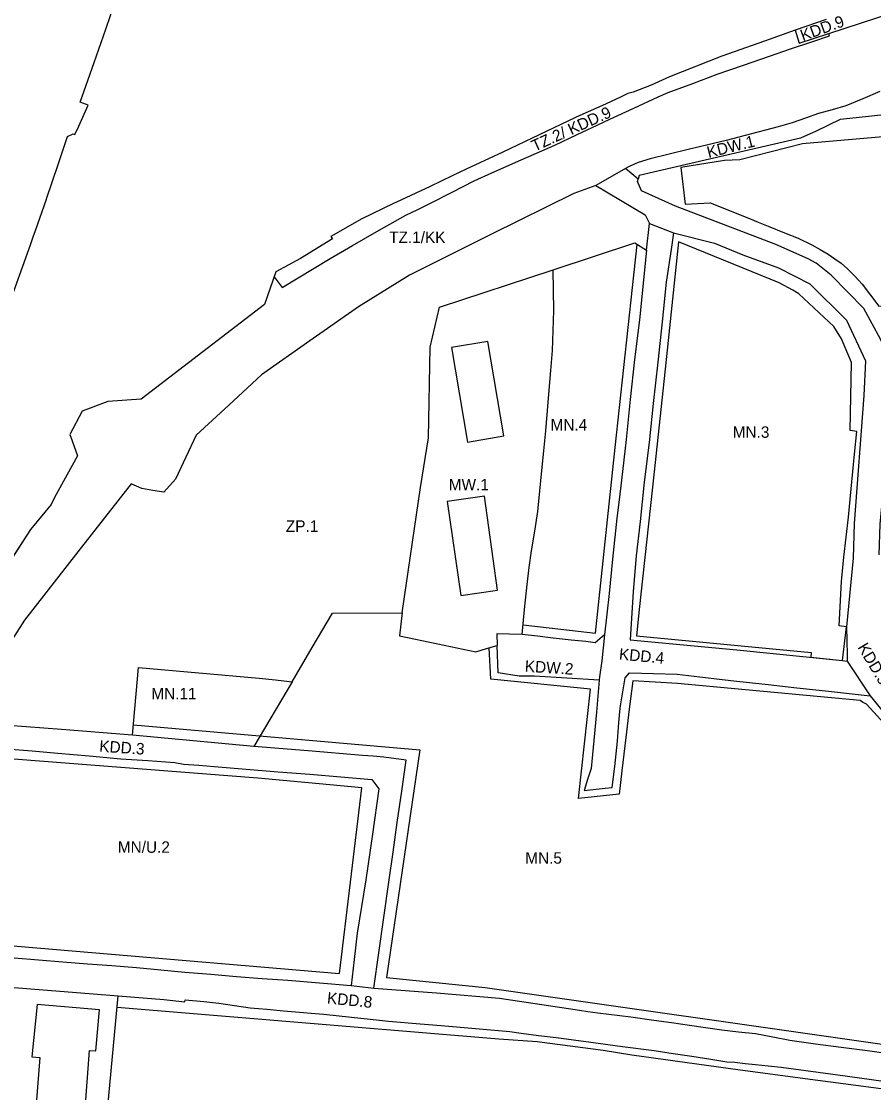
# Model space of a CAD drawing. Extents: x 7423274 to 7424514, y 5542390 to 5544261.
# Drawn here: x 7423710.5 to 7424007.3, y 5543609.4 to 5543982.5 of the extents above; entities that cross this region are included whole.
import ezdxf

# ---------------------------------------------------------------- set-up
doc = ezdxf.new("R2010")
doc.units = 0
for name, color, linetype in [('granica obszaru objętego planem', 7, 'Continuous'), ('LIN_Granica Planu', 7, 'Continuous'), ('linie rozgraniczające tereny o różnym przeznaczeniu lub różnych zasadach zagospodarowania', 7, 'Continuous'), ('nieprzekraczalna linia zabudowy', 7, 'Continuous'), ('oznaczenia terenów', 7, 'Continuous'), ('tereny dka ktorych obowiazuje_397', 7, 'Continuous')]:
    doc.layers.add(name, color=color, linetype=linetype)

msp = doc.modelspace()

# ---------------------------------------------------------------- linework, layer by layer
at = {"layer": 'granica obszaru objętego planem'}
msp.add_line((7423730.46, 5543946.09), (7423733.75, 5543953.36), dxfattribs=at)
for points in [[(7423733.75, 5543953.36), (7423730.98, 5543954.36), (7423735.85, 5543968.19), (7423739.86, 5543979.87), (7423744.43, 5543993.18), (7423748.18, 5544002.26)], [(7423630.4, 5543663.13), (7423628.64, 5543664.58), (7423644.74, 5543709.72), (7423662.88, 5543761.16), (7423686.37, 5543828.63), (7423694.83, 5543851.64), (7423703.37, 5543876.01), (7423705.32, 5543881.56), (7423705.6, 5543882.35), (7423713.61, 5543904.67), (7423714.59, 5543907.49), (7423715.34, 5543909.64), (7423719.18, 5543920.63), (7423719.32, 5543921.05), (7423723.14, 5543932.38), (7423726.53, 5543942.4), (7423728.54, 5543943.36), (7423729.11, 5543943.11), (7423730.46, 5543946.09)]]:
    msp.add_lwpolyline(points, dxfattribs=at)
at = {"layer": 'LIN_Granica Planu'}
msp.add_lwpolyline([(7423990.88, 5543983.19), (7423979.97, 5543979.44), (7423969.32, 5543975.68), (7423954.44, 5543970.42), (7423936.28, 5543963.17), (7423929.82, 5543960.34), (7423923.54, 5543957.83), (7423921.74, 5543957.37), (7423919.16, 5543956.16), (7423912.73, 5543953.13), (7423906.01, 5543950.18), (7423903.5, 5543949.08), (7423890.86, 5543943.04), (7423878.19, 5543937.02), (7423865.42, 5543931.03), (7423860.52, 5543928.68), (7423852.91, 5543925.04), (7423841.15, 5543919.53), (7423840.12, 5543919.05), (7423829.09, 5543913.75), (7423818.23, 5543907.57), (7423818.81, 5543906.81), (7423807.73, 5543899.89), (7423799.13, 5543895.27), (7423795.15, 5543883.92), (7423752.19, 5543850.9), (7423740.64, 5543850.15), (7423731.65, 5543846.8), (7423727.31, 5543838.61), (7423728.11, 5543836.41), (7423730.01, 5543831.23), (7423721.96, 5543816.67), (7423720.88, 5543814.22), (7423713.68, 5543805.49), (7423684.55, 5543760.67)], dxfattribs=at)
at = {"layer": 'linie rozgraniczające tereny o różnym przeznaczeniu lub różnych zasadach zagospodarowania'}
for p, q in [((7423990.88, 5543983.19), (7423979.97, 5543979.44)), ((7423979.97, 5543979.44), (7423969.32, 5543975.68)), ((7423969.32, 5543975.68), (7423954.44, 5543970.42)), ((7423954.44, 5543970.42), (7423936.28, 5543963.17)), ((7423936.28, 5543963.17), (7423929.82, 5543960.34)), ((7423929.82, 5543960.34), (7423923.54, 5543957.83)), ((7423919.16, 5543956.16), (7423912.73, 5543953.13)), ((7423921.74, 5543957.37), (7423919.16, 5543956.16)), ((7423923.54, 5543957.83), (7423921.74, 5543957.37)), ((7423912.73, 5543953.13), (7423906.01, 5543950.18)), ((7423903.5, 5543949.08), (7423890.86, 5543943.04)), ((7423906.01, 5543950.18), (7423903.5, 5543949.08)), ((7423890.86, 5543943.04), (7423878.19, 5543937.02)), ((7423878.19, 5543937.02), (7423865.42, 5543931.03)), ((7423860.52, 5543928.68), (7423852.91, 5543925.04)), ((7423865.42, 5543931.03), (7423860.52, 5543928.68)), ((7423920.97, 5543931.26), (7423910.55, 5543925.33)), ((7423852.91, 5543925.04), (7423841.15, 5543919.53)), ((7423840.12, 5543919.05), (7423829.09, 5543913.75)), ((7423841.15, 5543919.53), (7423840.12, 5543919.05)), ((7423829.09, 5543913.75), (7423818.23, 5543907.57)), ((7423929.32, 5543912.12), (7423937.66, 5543908.89)), ((7423818.81, 5543906.81), (7423807.73, 5543899.89)), ((7423818.23, 5543907.57), (7423818.81, 5543906.81)), ((7423807.73, 5543899.89), (7423799.13, 5543895.27)), ((7423799.13, 5543895.27), (7423795.15, 5543883.92)), ((7423795.15, 5543883.92), (7423752.19, 5543850.9)), ((7423740.64, 5543850.15), (7423731.65, 5543846.8)), ((7423752.19, 5543850.9), (7423740.64, 5543850.15)), ((7423731.65, 5543846.8), (7423727.31, 5543838.61)), ((7423727.31, 5543838.61), (7423728.11, 5543836.41)), ((7423728.11, 5543836.41), (7423730.01, 5543831.23)), ((7423730.01, 5543831.23), (7423721.96, 5543816.67)), ((7423721.96, 5543816.67), (7423720.88, 5543814.22)), ((7423720.88, 5543814.22), (7423713.68, 5543805.49)), ((7423713.68, 5543805.49), (7423684.55, 5543760.67)), ((7423998.16, 5543759.68), (7424006.1, 5543747.6)), ((7423804.77, 5543752.5), (7423791.41, 5543729.9))]:
    msp.add_line(p, q, dxfattribs=at)
for points in [[(7423991.76, 5543978.3), (7424019.83, 5543987.51), (7424014.59, 5543988.83)], [(7423798.55, 5543893.6), (7423801.31, 5543889.87), (7423818.07, 5543899.99), (7423825.76, 5543904.52), (7423835.09, 5543909.79), (7423844.42, 5543915.06), (7423848.62, 5543917.05), (7423852.81, 5543919.05), (7423860.49, 5543923.03), (7423868.16, 5543927.01), (7423874.34, 5543929.77), (7423884.55, 5543934.31), (7423891.78, 5543937.47), (7423896.27, 5543939.41), (7423904.11, 5543943.15), (7423911.04, 5543946.38), (7423915.45, 5543948.43), (7423923.88, 5543952.33), (7423932.31, 5543956.24), (7423935.73, 5543957.71), (7423944.32, 5543960.92), (7423952.91, 5543964.13), (7423961.98, 5543967.3), (7423971.05, 5543970.48), (7423978.42, 5543972.96), (7423985.79, 5543975.44), (7423992.01, 5543977.54), (7423991.76, 5543978.3)], [(7423979.97, 5543979.44), (7423981.44, 5543974.91), (7423991.76, 5543978.3)], [(7424009.49, 5543958.12), (7424003.59, 5543955.61), (7423997.7, 5543953.09), (7423992.95, 5543951.78), (7423988.2, 5543950.47), (7423983.6, 5543948.86), (7423979, 5543947.24), (7423974.12, 5543945.83), (7423962.62, 5543942.75), (7423956.01, 5543941.1), (7423942.79, 5543937.91), (7423929.57, 5543934.71), (7423925.31, 5543933.4), (7423921.74, 5543931.7), (7423920.97, 5543931.26)], [(7424061.6, 5543951.39), (7424050.54, 5543949.78), (7424037.51, 5543951.62), (7424023.67, 5543951.43), (7424011.93, 5543950.16), (7424001.33, 5543948.98), (7423995.7, 5543948.35), (7423987.33, 5543944.28), (7423981.88, 5543941.81), (7423950.16, 5543934.53), (7423925.71, 5543928.9), (7423925.33, 5543927.63), (7423925.33, 5543927.61), (7423925.32, 5543927.6), (7423925.28, 5543927.6)], [(7423925.28, 5543927.6), (7423920.97, 5543931.26)], [(7423910.55, 5543925.33), (7423902.95, 5543922.56), (7423874.29, 5543908.37), (7423845.63, 5543894.18), (7423827.93, 5543883.07), (7423811.01, 5543871.21), (7423794.09, 5543859.36), (7423782.75, 5543848.88), (7423771.41, 5543838.41), (7423767.76, 5543830.75), (7423764.11, 5543823.09), (7423760.13, 5543818.51), (7423756.26, 5543819.17), (7423752.39, 5543819.83), (7423748.68, 5543821.45), (7423730.12, 5543797.71), (7423711.56, 5543773.96), (7423700.22, 5543756.26), (7423686.45, 5543734.78), (7423680.78, 5543725.93), (7423673.32, 5543711.94), (7423663.07, 5543692.74), (7423660.29, 5543687.53), (7423669.49, 5543682.49)], [(7423910.55, 5543925.33), (7423927.76, 5543915.14), (7423929.32, 5543912.12)], [(7424009.26, 5543796.75), (7424009.59, 5543807.35), (7424012.28, 5543835.77), (7424014.01, 5543851.2), (7424013.93, 5543852.09), (7424012.86, 5543864.73), (7424009.71, 5543871.85), (7424004, 5543882.5), (7423992.6, 5543894.18), (7423987.31, 5543898.3), (7423984.61, 5543899.85), (7423973.32, 5543904.78), (7423938.39, 5543918.19), (7423926.52, 5543923.51), (7423925.07, 5543926.76), (7423925.28, 5543927.6)], [(7423928.26, 5543902.79), (7423929.32, 5543912.12)], [(7423937.66, 5543908.89), (7423936.78, 5543903.02), (7423935.08, 5543891.66), (7423933.74, 5543877.91), (7423932.14, 5543863.78), (7423930.51, 5543849.47), (7423929.19, 5543835.82), (7423927.47, 5543821.98), (7423926.06, 5543808.27), (7423924.67, 5543796.35), (7423923.64, 5543783.96), (7423922.58, 5543767.11), (7423959.76, 5543763.59), (7423996.57, 5543759.93), (7423998.16, 5543759.68)], [(7423937.66, 5543908.89), (7423951.93, 5543905.24), (7423961.85, 5543901.16), (7423974.24, 5543896.72), (7423985.15, 5543891.08), (7423997.92, 5543878.46), (7424004.54, 5543864.28), (7424004, 5543852.26), (7424000.56, 5543807.67), (7424000.24, 5543795.55), (7423997.86, 5543771.66), (7423998.12, 5543761.86), (7423998.16, 5543759.68)], [(7423895.72, 5543895.99), (7423924.2, 5543905.38), (7423928.26, 5543902.79)], [(7423928.26, 5543902.79), (7423925.81, 5543878.59), (7423924.04, 5543864.78), (7423922.58, 5543850.81), (7423921.1, 5543836.89), (7423919.55, 5543822.77), (7423918.67, 5543815.83), (7423917.87, 5543809.45), (7423916.41, 5543795.2), (7423915.21, 5543783.24), (7423913.66, 5543768.86)], [(7423843.16, 5543776.46), (7423849.54, 5543820.19), (7423852.35, 5543837.52), (7423852.89, 5543869), (7423856.14, 5543883), (7423895.72, 5543895.99)], [(7423884.89, 5543768.93), (7423885.78, 5543777.67), (7423886.66, 5543786.41), (7423887.41, 5543792.26), (7423888.15, 5543798.11), (7423889.28, 5543804.95), (7423890.4, 5543811.78), (7423890.75, 5543815.38), (7423891.09, 5543818.98), (7423891.42, 5543822.52), (7423891.76, 5543826.06), (7423892.45, 5543832.98), (7423893.14, 5543839.89), (7423893.72, 5543846.96), (7423894.3, 5543854.03), (7423894.88, 5543860.94), (7423895.46, 5543867.85), (7423895.69, 5543874.86), (7423895.91, 5543881.87), (7423895.82, 5543888.93), (7423895.72, 5543895.99)], [(7423804.77, 5543752.5), (7423811.79, 5543764.44), (7423818.81, 5543776.38), (7423843.16, 5543776.46)], [(7423843.16, 5543776.46), (7423842.69, 5543772.5), (7423842.21, 5543768.54), (7423855.5, 5543765.75), (7423868.8, 5543762.95), (7423872.5, 5543764.04), (7423876.2, 5543765.14)], [(7423884.89, 5543768.93), (7423876.12, 5543769.24), (7423876.2, 5543765.14)], [(7423913.66, 5543768.86), (7423910.38, 5543766.1), (7423907.12, 5543766.47), (7423902.03, 5543767.02), (7423895.68, 5543767.73), (7423890.29, 5543768.33), (7423884.89, 5543768.93)], [(7423913.66, 5543768.86), (7423912.66, 5543759.73), (7423911.89, 5543754.18), (7423911.73, 5543753.06), (7423911.73, 5543753.03)], [(7423997.86, 5543771.66), (7423997.86, 5543771.66)], [(7423911.73, 5543753.03), (7423889.18, 5543754.49), (7423883.86, 5543754.42), (7423876.57, 5543755.62), (7423876.2, 5543765.14)], [(7423749.2, 5543733.94), (7423751.28, 5543757.44), (7423772.28, 5543755.62), (7423793.28, 5543753.8), (7423799.03, 5543753.15), (7423804.77, 5543752.5)], [(7423911.73, 5543753.03), (7423911.29, 5543747.46), (7423910.85, 5543741.86), (7423909.91, 5543732.08), (7423908.96, 5543722.3), (7423907.7, 5543718.41), (7423906.55, 5543714.66), (7423913.88, 5543715.44), (7423916.33, 5543715.7), (7423917.16, 5543722.98), (7423918.12, 5543731.82), (7423918.25, 5543733.39), (7423918.65, 5543738.28), (7423919.04, 5543743.17), (7423919.2, 5543744.1), (7423920.03, 5543748.96), (7423920.85, 5543753.81), (7423922.36, 5543755.63), (7423930.66, 5543755.39), (7423938.95, 5543755.15), (7423946.78, 5543754.24), (7423954.6, 5543753.32), (7423959.65, 5543752.75), (7423965.13, 5543752.12), (7423970.62, 5543751.48), (7423980.61, 5543750.42), (7423990.6, 5543749.35), (7424006.1, 5543747.6)], [(7424006.1, 5543747.6), (7424014.31, 5543737.6), (7424018.89, 5543732.62), (7424020.25, 5543731.58), (7424031, 5543723.4), (7424032.09, 5543721.82), (7424032.78, 5543720.24), (7424033.42, 5543714.89), (7424033.72, 5543711.43), (7424032.26, 5543690.72), (7424032.15, 5543687.75), (7424032.14, 5543665.88), (7424034.16, 5543646.49), (7424038.33, 5543626.9)], [(7423749.2, 5543733.94), (7423724.47, 5543735.81), (7423699.74, 5543737.68), (7423684.62, 5543710.08), (7423678.21, 5543698.4), (7423674.43, 5543691.51)], [(7423791.41, 5543729.9), (7423770.3, 5543731.92), (7423749.2, 5543733.94)], [(7423705.34, 5543729.14), (7423714.23, 5543728.38), (7423723.12, 5543727.61), (7423734.09, 5543726.66), (7423745.07, 5543725.7), (7423754.47, 5543725.05), (7423763.87, 5543724.4), (7423766.98, 5543723.83), (7423772.32, 5543723.4), (7423777.66, 5543722.96), (7423783.24, 5543722.5), (7423788.82, 5543722.05), (7423799.88, 5543721.17), (7423810.94, 5543720.3), (7423821.77, 5543719.38), (7423832.59, 5543718.45), (7423835.01, 5543715.21), (7423832.75, 5543699.35), (7423830.48, 5543683.49), (7423828.96, 5543674.19), (7423827.45, 5543664.89), (7423826.38, 5543655.79), (7423825.31, 5543646.69)], [(7423833.22, 5543645.8), (7423838.46, 5543682.67), (7423839.94, 5543693.08), (7423841.42, 5543703.48), (7423843, 5543714.34), (7423844.57, 5543725.21), (7423836.75, 5543726.24), (7423833.02, 5543726.54), (7423829.28, 5543726.85), (7423810.34, 5543728.38), (7423791.41, 5543729.9)], [(7423666.55, 5543659.55), (7423672.05, 5543659.11), (7423688.53, 5543657.81), (7423699.49, 5543656.95), (7423707.96, 5543656.29), (7423716.43, 5543655.62), (7423724.94, 5543654.95), (7423733.45, 5543654.28), (7423742, 5543653.62), (7423750.56, 5543652.95), (7423759, 5543652.17), (7423767.44, 5543651.38), (7423776.41, 5543650.58), (7423785.37, 5543649.77), (7423794.33, 5543649.16), (7423803.3, 5543648.54), (7423814.3, 5543647.62), (7423825.31, 5543646.69)], [(7423665.82, 5543649.26), (7423705, 5543646.16), (7423744.17, 5543643.05)], [(7423825.31, 5543646.69), (7423833.22, 5543645.8)], [(7423833.22, 5543645.8), (7423855.12, 5543644.09), (7423877.01, 5543642.26), (7423901.03, 5543638.63), (7423904.85, 5543638.05), (7423907.82, 5543637.66), (7423911.29, 5543637.21), (7423922.79, 5543635.71), (7423930.81, 5543634.65), (7423937, 5543633.76), (7423943.18, 5543632.87), (7423948.81, 5543632.05), (7423954.44, 5543631.24), (7423960.32, 5543630.59), (7423966.2, 5543629.94), (7423972.21, 5543628.76), (7423978.22, 5543627.58), (7423987.15, 5543626.38), (7423996.08, 5543625.19), (7424005.18, 5543623.99), (7424014.28, 5543622.79)], [(7423745.12, 5543514.34), (7423739.99, 5543533.2), (7423734.85, 5543552.05), (7423742.81, 5543553.35), (7423750.78, 5543554.65), (7423748.56, 5543563.58), (7423746.35, 5543572.52), (7423741.99, 5543572.99), (7423737.63, 5543573.46), (7423740.9, 5543608.25), (7423744.17, 5543643.05)], [(7423744.17, 5543643.05), (7423760.08, 5543641.79), (7423767.46, 5543641.01), (7423767.52, 5543641.66), (7423773.98, 5543641.06), (7423779.26, 5543640.48), (7423790.15, 5543638.88), (7423795.99, 5543638.4), (7423801.82, 5543637.91), (7423807.31, 5543637.44), (7423812.8, 5543636.97), (7423815.79, 5543636.65), (7423825.52, 5543635.62), (7423835.24, 5543634.58), (7423838.38, 5543634.3), (7423849.37, 5543633.32), (7423856.72, 5543632.71), (7423868.66, 5543631.67), (7423880.6, 5543630.63), (7423884.57, 5543630.11), (7423890.64, 5543629.32), (7423896.71, 5543628.52), (7423902.78, 5543627.73), (7423908.84, 5543626.93), (7423919.89, 5543625.48), (7423930.94, 5543624.02), (7423937.5, 5543623.04), (7423944.05, 5543622.05), (7423950.61, 5543621.07), (7423956.23, 5543620.14), (7423959.04, 5543619.93), (7423962.62, 5543619.52), (7423966.2, 5543619.11), (7423970.67, 5543618.65), (7423975.15, 5543618.19), (7423983.77, 5543617.04), (7423992.38, 5543615.89), (7424001.65, 5543614.58), (7424013.28, 5543613.04)]]:
    msp.add_lwpolyline(points, dxfattribs=at)
at = {"layer": 'nieprzekraczalna linia zabudowy'}
for p, q in [((7423872.95, 5543871.08), (7423860.33, 5543868.94)), ((7423860.33, 5543868.94), (7423865.92, 5543836.01)), ((7423878.54, 5543838.15), (7423872.95, 5543871.08)), ((7423865.92, 5543836.01), (7423878.54, 5543838.15)), ((7423871.77, 5543817.09), (7423858.8, 5543815.28)), ((7423876.35, 5543784.36), (7423871.77, 5543817.09)), ((7423858.8, 5543815.28), (7423863.59, 5543782.55)), ((7423863.59, 5543782.55), (7423876.35, 5543784.36)), ((7423874.05, 5543753.4), (7423873.41, 5543764.31)), ((7423908.75, 5543749.93), (7423874.05, 5543753.4)), ((7423904.58, 5543711.8), (7423908.75, 5543749.93)), ((7424003.52, 5543745.44), (7424002.64, 5543745.94)), ((7423749.51, 5543737.43), (7423849.22, 5543728.79)), ((7423849.22, 5543728.79), (7423837.7, 5543649.44)), ((7423918.68, 5543713.33), (7423904.58, 5543711.8)), ((7423673.23, 5543663.39), (7423821.25, 5543650.85)), ((7423715.94, 5543640.12), (7423714.13, 5543621.85)), ((7423737.72, 5543638.17), (7423715.94, 5543640.12)), ((7423736.42, 5543623.96), (7423737.72, 5543638.17)), ((7423890.12, 5543627.03), (7423876.8, 5543627.99)), ((7423734.16, 5543624.08), (7423736.42, 5543623.96)), ((7423716.94, 5543621.63), (7423713.15, 5543575.42)), ((7423714.13, 5543621.85), (7423716.94, 5543621.63))]:
    msp.add_line(p, q, dxfattribs=at)
for points in [[(7424053.24, 5543946.06), (7424053.24, 5543946.06), (7424053.24, 5543946.06), (7424053.24, 5543946.06), (7423982.54, 5543939.91), (7423960.7, 5543934.36)], [(7423955.46, 5543934.07), (7423940.25, 5543931.64)], [(7423960.7, 5543934.36), (7423955.46, 5543934.07)], [(7423940.25, 5543931.64), (7423940.25, 5543931.64), (7423941.76, 5543918.85), (7423950.39, 5543919.32)], [(7423950.39, 5543919.32), (7423963.48, 5543914.06), (7423967.18, 5543912.57), (7423970.64, 5543911.16), (7423976.27, 5543908.88), (7423981.11, 5543906.98), (7423985.86, 5543904.69), (7423988.77, 5543903.12), (7423991.47, 5543901.48), (7423993.9, 5543899.86), (7423996.01, 5543898.27), (7423998.22, 5543896.33), (7424000.76, 5543893.82), (7424003.4, 5543891), (7424009.18, 5543883.33), (7424009.18, 5543883.33), (7424010.28, 5543883.42), (7424010.92, 5543877.97), (7424013, 5543878.3), (7424013.93, 5543872.51), (7424015.35, 5543865.04), (7424017.04, 5543865.32), (7424017.82, 5543858.83), (7424018.03, 5543854.34)], [(7423885.29, 5543772.27), (7423910.49, 5543769.39), (7423917.3, 5543834.05), (7423923.39, 5543889.86), (7423925.03, 5543904.85)], [(7423939.41, 5543905.7), (7423934.93, 5543863.57), (7423930.92, 5543825.65), (7423925.67, 5543777.63), (7423924.75, 5543768.51)], [(7423999.69, 5543863.74), (7423999.69, 5543863.74), (7423999.69, 5543863.74), (7423996.17, 5543871.97), (7423993.53, 5543876.25), (7423981.25, 5543887.64), (7423979.25, 5543888.9), (7423974.44, 5543891.46), (7423939.41, 5543905.7)], [(7424001.51, 5543839.68), (7423999.21, 5543840.01), (7423999.69, 5543863.74)], [(7423995.39, 5543771.93), (7423996.18, 5543787.42), (7423997.02, 5543795.91), (7423998.56, 5543809.87), (7423999.53, 5543819.73), (7424000.69, 5543831.78), (7424001.51, 5543839.68), (7424001.51, 5543839.68)], [(7423985.63, 5543762.72), (7423985.45, 5543761.1), (7423996.57, 5543759.93), (7423997.86, 5543771.66), (7423995.39, 5543771.93)], [(7423924.75, 5543768.51), (7423985.63, 5543762.72), (7423985.63, 5543762.72)], [(7423923.46, 5543752.84), (7423922.2, 5543742.89), (7423921.01, 5543733.04), (7423919.59, 5543721.43), (7423918.68, 5543713.33)], [(7424002.64, 5543745.94), (7423939.08, 5543751.92), (7423923.46, 5543752.84)], [(7424028.68, 5543720.51), (7424014.7, 5543733.87), (7424004.92, 5543744.63), (7424003.52, 5543745.44)], [(7423829.09, 5543715.59), (7423810.54, 5543717.34), (7423792.87, 5543718.94), (7423707.82, 5543725.53)], [(7423821.24, 5543650.83), (7423825.07, 5543682.72), (7423829.09, 5543715.59)], [(7423837.7, 5543649.44), (7423872.04, 5543646.02), (7424011.15, 5543626.09), (7424026.85, 5543624.64)], [(7423876.8, 5543627.99), (7423876.8, 5543627.99), (7423743.78, 5543638.96)], [(7424039.93, 5543606.59), (7424020.52, 5543609.24), (7423987.89, 5543613.53), (7423960.85, 5543617.16), (7423923.09, 5543622.46), (7423913.13, 5543624.02), (7423890.12, 5543627.03)], [(7423730.35, 5543574.31), (7423731.42, 5543586.5), (7423734.16, 5543624.08)]]:
    msp.add_lwpolyline(points, dxfattribs=at)
at = {"layer": 'tereny dka ktorych obowiazuje_397'}
for points in [[(7423705.6, 5543882.35), (7423713.61, 5543904.67), (7423714.59, 5543907.49), (7423715.34, 5543909.64), (7423719.18, 5543920.63), (7423719.32, 5543921.05), (7423723.14, 5543932.38), (7423726.53, 5543942.4), (7423728.54, 5543943.36), (7423729.11, 5543943.11), (7423730.46, 5543946.09), (7423733.75, 5543953.36), (7423730.98, 5543954.36), (7423735.85, 5543968.19), (7423739.86, 5543979.87), (7423744.43, 5543993.18)], [(7423990.88, 5543983.19), (7423979.97, 5543979.44), (7423969.32, 5543975.68), (7423954.44, 5543970.42), (7423936.28, 5543963.17), (7423929.82, 5543960.34), (7423923.54, 5543957.83), (7423921.74, 5543957.37), (7423919.16, 5543956.16), (7423912.73, 5543953.13), (7423906.01, 5543950.18), (7423903.5, 5543949.08), (7423890.86, 5543943.04), (7423878.19, 5543937.02), (7423865.42, 5543931.03), (7423860.52, 5543928.68), (7423852.91, 5543925.04), (7423841.15, 5543919.53), (7423840.12, 5543919.05), (7423829.09, 5543913.75), (7423818.23, 5543907.57), (7423818.81, 5543906.81), (7423807.73, 5543899.89), (7423799.13, 5543895.27), (7423795.15, 5543883.92), (7423752.19, 5543850.9), (7423740.64, 5543850.15), (7423731.65, 5543846.8), (7423727.31, 5543838.61), (7423728.11, 5543836.41), (7423730.01, 5543831.23), (7423721.96, 5543816.67), (7423720.88, 5543814.22), (7423713.68, 5543805.49), (7423684.55, 5543760.67)]]:
    msp.add_lwpolyline(points, dxfattribs=at)

# ---------------------------------------------------------------- texts
at = {"layer": 'oznaczenia terenów'}
for s, rotation, p in [('KDD.9', 19.9318, (7423982.69, 5543975.6)), ('TZ.2/ KDD.9', 24.4471, (7423889.29, 5543937.1)), ('KDW.1', 13.914, (7423949.84, 5543934.95)), ('KDD.5', 300.9466, (7424001.62, 5543764.52)), ('KDD.4', 354.4715, (7423918.53, 5543760.25)), ('KDW.2', 356.2567, (7423885.75, 5543756.02)), ('KDD.3', 356.1008, (7423737.51, 5543728.15)), ('KDD.8', 354.1971, (7423816.81, 5543640.44))]:
    msp.add_text(s, height=4, rotation=rotation, dxfattribs=at).set_placement(p)
for s, p in [('TZ.1/KK', (7423838.59, 5543905.33)), ('MN.4', (7423894.81, 5543840.01)), ('MN.3', (7423958.27, 5543837.47)), ('MW.1', (7423859.36, 5543819.16)), ('ZP.1', (7423802.6, 5543804.72)), ('MN.11', (7423755.73, 5543746.36)), ('MN/U.2', (7423744.07, 5543692.9)), ('MN.5', (7423885.99, 5543689.12))]:
    msp.add_text(s, height=4, dxfattribs=at).set_placement(p)

doc.saveas('drawing.dxf')
